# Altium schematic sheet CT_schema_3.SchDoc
size 287 x 169 mm
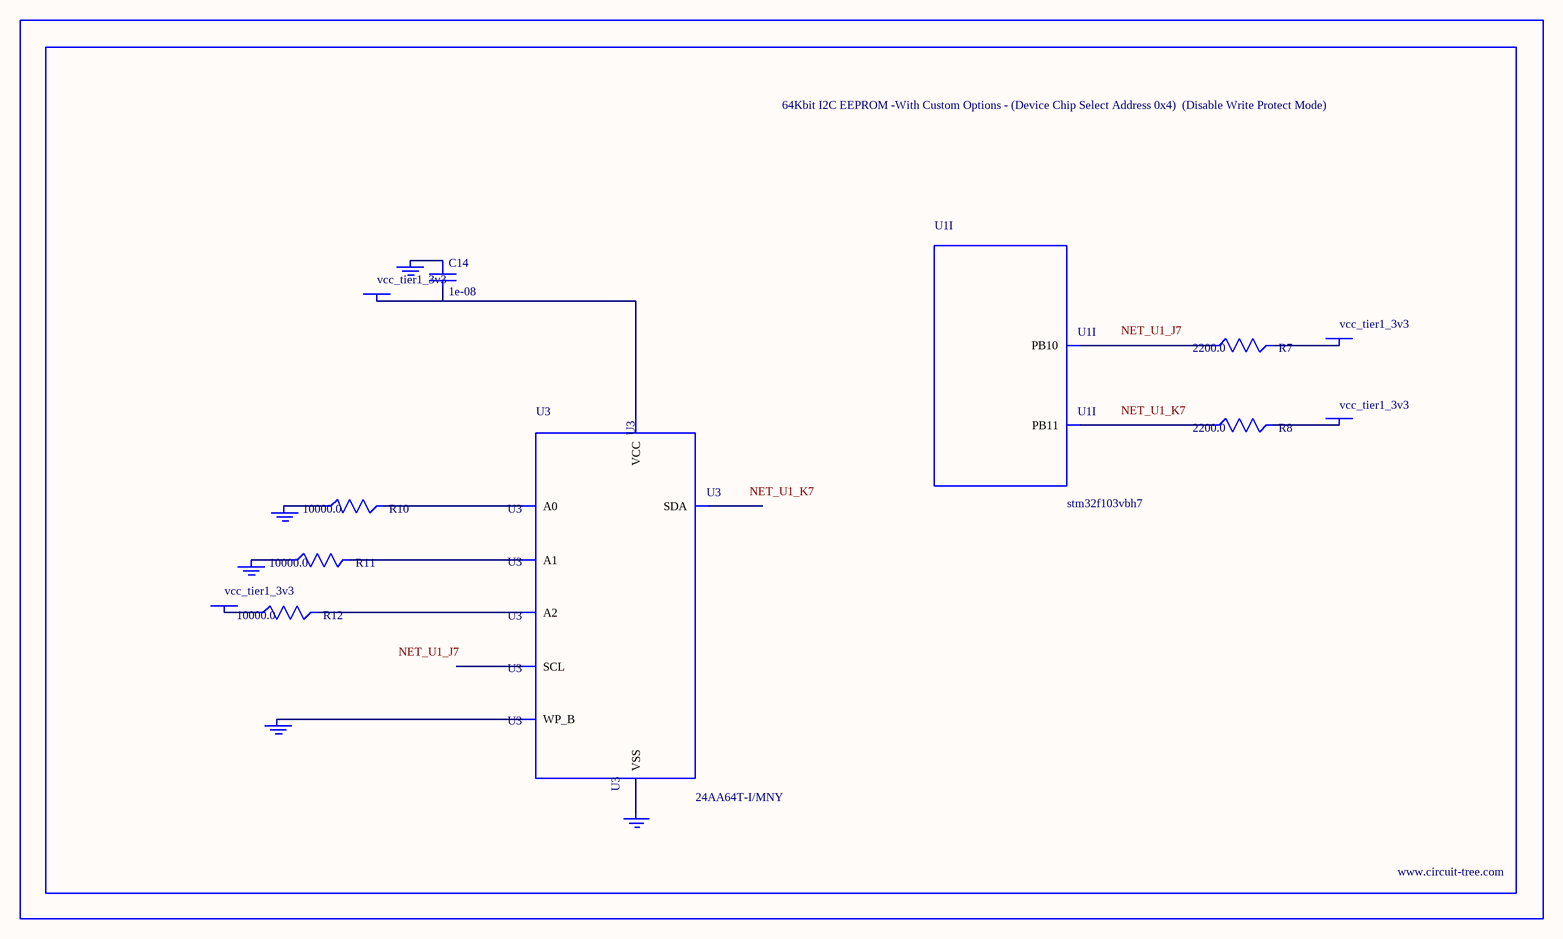
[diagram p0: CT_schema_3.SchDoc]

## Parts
BORDER2  (no value)
C14  1e-08  [C0402]
GND_INSTANCE_2_0  (no value)
GND_INSTANCE_2_1  (no value)
GND_INSTANCE_2_2  (no value)
GND_INSTANCE_2_3  (no value)
GND_INSTANCE_2_4  (no value)
POWER_INSTANCE_2_0  vcc_tier1_3v3
POWER_INSTANCE_2_1  vcc_tier1_3v3
POWER_INSTANCE_2_2  vcc_tier1_3v3
POWER_INSTANCE_2_3  vcc_tier1_3v3
R7  2200.0  [R0603]
R8  2200.0  [R0603]
R10  10000.0  [R0603]
R11  10000.0  [R0603]
R12  10000.0  [R0603]
U1  stm32f103vbh7  [LFBGA100]  (part I of 10)
U3  24AA64T-I/MNY  [TDFN-8/6MM]

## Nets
NetC14_1: C14.1 GND_INSTANCE_2_3.0(GND)
NetC14_2: C14.2 POWER_INSTANCE_2_1.0(PWR) U3.8(VCC)
NetGND_INSTANCE_2_0_0: GND_INSTANCE_2_0.0(GND) R10.1
NetGND_INSTANCE_2_1_0: GND_INSTANCE_2_1.0(GND) R11.1
NetGND_INSTANCE_2_2_0: GND_INSTANCE_2_2.0(GND) U3.7(WP_B)
NetGND_INSTANCE_2_4_0: GND_INSTANCE_2_4.0(GND) U3.4(VSS)
NetPOWER_INSTANCE_2_0_0: POWER_INSTANCE_2_0.0(PWR) R12.1
NetPOWER_INSTANCE_2_2_0: POWER_INSTANCE_2_2.0(PWR) R7.2
NetPOWER_INSTANCE_2_3_0: POWER_INSTANCE_2_3.0(PWR) R8.2
NetR7_1: R7.1 U1.J7(PB10)
NetR8_1: R8.1 U1.K7(PB11)
NetR10_2: R10.2 U3.1(A0)
NetR11_2: R11.2 U3.2(A1)
NetR12_2: R12.2 U3.3(A2)

Not connected (* = marked no-connect by the designer): U3 5(SDA) 6(SCL)

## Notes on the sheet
- Labels drawn without touching a wire or pin: NET_U1_J7, NET_U1_K7

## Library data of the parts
BORDER2 = BORDER_PAGE2
C14 = C0402C103K3RAC
GND_INSTANCE_2_0-GND_INSTANCE_2_4 = GND
POWER_INSTANCE_2_0-POWER_INSTANCE_2_3 = PWR
R7 R8 = RC0603JR-072K2L
R10-R12 = RC0603JR-0710KL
